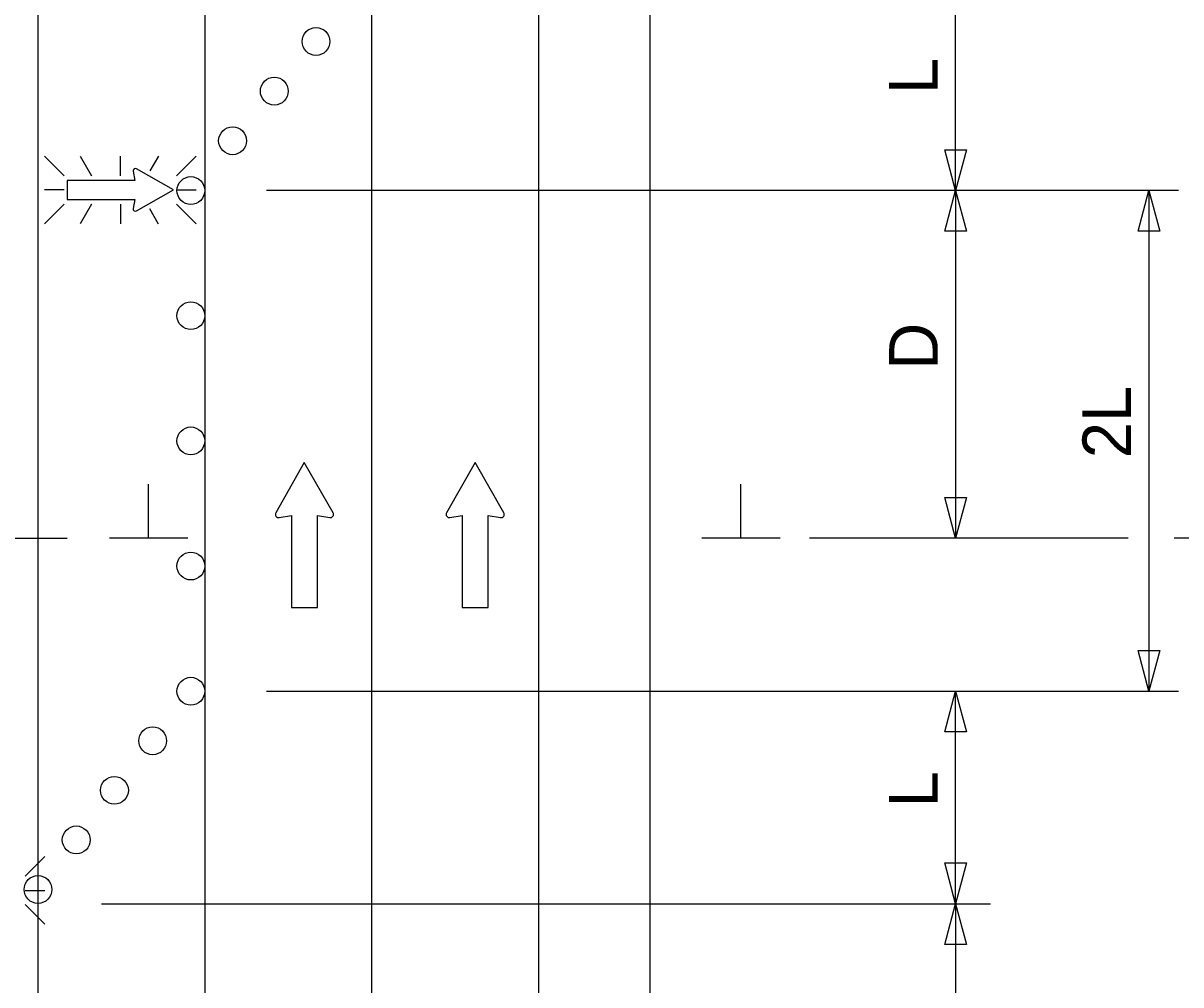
# Model space of a CAD drawing. Extents: x 16744 to 19504, y 5731 to 6974.
# Drawn here: x 17971.4 to 18137.9, y 6414.2 to 6552.5 of the extents above; entities that cross this region are included whole.
import ezdxf

# ---------------------------------------------------------------- set-up
doc = ezdxf.new("R2010")
doc.units = 0
for name, color, linetype in [('ALI_LEGAL_EX', 7, 'Continuous'), ('MT_SCRATCH_LEVEL_E', 7, 'Continuous'), ('PAVT_EDGE_EX', 7, 'Continuous'), ('TRAFFIC_SIGNS_PR', 7, 'Continuous'), ('TYPICAL_TEXT_DIMEN_PR', 7, 'Continuous')]:
    doc.layers.add(name, color=color, linetype=linetype)

msp = doc.modelspace()

# ---------------------------------------------------------------- linework, layer by layer
at = {"layer": 'ALI_LEGAL_EX'}
for p, q in [((17997.5, 6891.16), (17997.5, 6061.98)), ((18021.5, 6891.16), (18021.5, 6061.98)), ((18021.5, 6891.16), (18021.5, 6061.98))]:
    msp.add_line(p, q, dxfattribs=at)
for points in [[(17997.5, 6491.16), (17997.5, 6466.16)], [(18021.5, 6491.16), (18021.5, 6466.16)]]:
    msp.add_lwpolyline(points, dxfattribs=at)
at = {"layer": 'MT_SCRATCH_LEVEL_E'}
for p, q in [((18011.82, 6489.34), (18007.71, 6482.1)), ((18011.82, 6489.34), (18007.71, 6482.1)), ((18015.97, 6482.1), (18011.82, 6489.34)), ((18015.97, 6482.1), (18011.82, 6489.34)), ((18036.38, 6489.34), (18032.27, 6482.1)), ((18036.38, 6489.34), (18032.27, 6482.1)), ((18040.53, 6482.1), (18036.38, 6489.34)), ((18040.53, 6482.1), (18036.38, 6489.34)), ((18008.19, 6481.41), (18009.97, 6481.73)), ((18008.19, 6481.41), (18009.97, 6481.73)), ((18009.97, 6481.73), (18009.97, 6468.47)), ((18009.97, 6481.73), (18009.97, 6468.47)), ((18013.71, 6468.47), (18013.71, 6481.73)), ((18013.71, 6481.73), (18015.49, 6481.41)), ((18013.71, 6468.47), (18013.71, 6481.73)), ((18013.71, 6481.73), (18015.49, 6481.41)), ((18032.75, 6481.41), (18034.53, 6481.73)), ((18032.75, 6481.41), (18034.53, 6481.73)), ((18034.53, 6481.73), (18034.53, 6468.47)), ((18034.53, 6481.73), (18034.53, 6468.47)), ((18038.27, 6468.47), (18038.27, 6481.73)), ((18038.27, 6481.73), (18040.05, 6481.41)), ((18038.27, 6468.47), (18038.27, 6481.73)), ((18038.27, 6481.73), (18040.05, 6481.41)), ((18009.97, 6468.47), (18013.71, 6468.47)), ((18009.97, 6468.47), (18013.71, 6468.47)), ((18034.53, 6468.47), (18038.27, 6468.47)), ((18034.53, 6468.47), (18038.27, 6468.47))]:
    msp.add_line(p, q, dxfattribs=at)
for centre, start, end in [((18008.12, 6481.87), 150.4248, 279.9638), ((18008.12, 6481.87), 150.4248, 279.9638), ((18015.56, 6481.87), 260.0362, 29.7731), ((18015.56, 6481.87), 260.0362, 29.7731), ((18032.68, 6481.87), 150.4248, 279.9638), ((18032.68, 6481.87), 150.4248, 279.9638), ((18040.12, 6481.87), 260.0362, 29.7731), ((18040.12, 6481.87), 260.0362, 29.7731)]:
    msp.add_arc(centre, 0.463, start, end, dxfattribs=at)
at = {"layer": 'PAVT_EDGE_EX'}
for p, q in [((17973.5, 6891.16), (17973.5, 6061.98)), ((17973.5, 6891.16), (17973.5, 6061.98)), ((18045.5, 6891.16), (18045.5, 6061.98)), ((18061.5, 6891.16), (18061.5, 6061.98))]:
    msp.add_line(p, q, dxfattribs=at)
at = {"layer": 'TRAFFIC_SIGNS_PR'}
for p, q in [((17977.28, 6530.55), (17974.46, 6533.37)), ((17979.58, 6533.37), (17981.2, 6530.55)), ((17985.36, 6530.55), (17985.36, 6533.37)), ((17990.83, 6533.37), (17989.62, 6531.27)), ((17996.27, 6533.36), (17993.45, 6530.55)), ((17977.28, 6528.52), (17974.46, 6528.52)), ((17993.45, 6528.52), (17996.27, 6528.52)), ((17977.28, 6526.48), (17974.46, 6523.66)), ((17981.23, 6526.48), (17979.6, 6523.66)), ((17985.36, 6526.48), (17985.36, 6523.66)), ((17996.27, 6523.66), (17993.45, 6526.48)), ((17989.55, 6525.85), (17990.81, 6523.66)), ((17974.51, 6432.65), (17971.69, 6429.83)), ((17971.69, 6427.8), (17974.51, 6427.8)), ((17974.51, 6422.95), (17971.69, 6425.77))]:
    msp.add_line(p, q, dxfattribs=at)
for points in [[(17987.19, 6531.2), (17987.42, 6529.9), (17977.7, 6529.9), (17977.7, 6527.16), (17987.42, 6527.16), (17987.19, 6525.85)], [(17987.69, 6525.5), (17993, 6528.52), (17987.69, 6531.56)]]:
    msp.add_lwpolyline(points, dxfattribs=at)
for centre in [(18013.5, 6549.87), (18007.5, 6542.73), (18001.5, 6535.59), (17995.5, 6528.44), (17995.5, 6510.44), (17995.5, 6492.44), (17995.5, 6474.44), (17995.5, 6456.44), (17990.01, 6449.31), (17984.51, 6442.19), (17979.01, 6435.06), (17973.51, 6427.93)]:
    msp.add_circle(centre, 2, dxfattribs=at)
for centre, start, end in [((17987.53, 6531.26), 61.4833, 189.9593), ((17987.53, 6525.8), 170.7308, 298.8916)]:
    msp.add_arc(centre, 0.341, start, end, dxfattribs=at)
at = {"layer": 'TYPICAL_TEXT_DIMEN_PR'}
for p, q in [((18105.5, 6528.44), (18105.5, 6559.01)), ((18105.5, 6528.44), (18103.93, 6534.31)), ((18103.93, 6534.31), (18105.5, 6534.31)), ((18105.5, 6534.31), (18107.07, 6534.31)), ((18107.07, 6534.31), (18105.5, 6528.44)), ((18137.55, 6528.44), (18006.4, 6528.44)), ((18103.93, 6522.58), (18105.5, 6528.44)), ((18105.5, 6528.44), (18105.5, 6478.44)), ((18105.5, 6528.44), (18107.07, 6522.58)), ((18131.74, 6522.58), (18133.31, 6528.44)), ((18133.31, 6528.44), (18134.88, 6522.58)), ((18133.31, 6528.44), (18133.31, 6456.44)), ((18105.5, 6522.58), (18103.93, 6522.58)), ((18107.07, 6522.58), (18105.5, 6522.58)), ((18133.31, 6522.58), (18131.74, 6522.58)), ((18134.88, 6522.58), (18133.31, 6522.58)), ((17989.43, 6478.44), (17989.43, 6486.23)), ((18074.63, 6478.44), (18074.63, 6486.23)), ((18105.5, 6478.44), (18103.93, 6484.31)), ((18103.93, 6484.31), (18105.5, 6484.31)), ((18105.5, 6484.31), (18107.07, 6484.31)), ((18107.07, 6484.31), (18105.5, 6478.44)), ((18133.31, 6483.31), (18133.31, 6479.55)), ((17899.85, 6478.44), (17977.7, 6478.44)), ((17995.05, 6478.44), (17983.8, 6478.44)), ((18080.25, 6478.44), (18069, 6478.44)), ((18130.32, 6478.44), (18084.5, 6478.44)), ((18174.21, 6478.44), (18136.94, 6478.44)), ((18133.31, 6456.44), (18131.74, 6462.31)), ((18131.74, 6462.31), (18133.31, 6462.31)), ((18133.31, 6462.31), (18134.88, 6462.31)), ((18134.88, 6462.31), (18133.31, 6456.44)), ((18006.4, 6456.44), (18137.55, 6456.44)), ((18103.93, 6450.58), (18105.5, 6456.44)), ((18105.5, 6425.88), (18105.5, 6456.44)), ((18105.5, 6456.44), (18107.07, 6450.58)), ((18105.5, 6450.58), (18103.93, 6450.58)), ((18107.07, 6450.58), (18105.5, 6450.58)), ((18105.5, 6425.88), (18103.93, 6431.74)), ((18103.93, 6431.74), (18105.5, 6431.74)), ((18105.5, 6431.74), (18107.07, 6431.74)), ((18107.07, 6431.74), (18105.5, 6425.88)), ((17982.67, 6425.88), (18110.5, 6425.88)), ((18103.93, 6420.02), (18105.5, 6425.88)), ((18105.5, 6425.88), (18105.5, 6377.89)), ((18105.5, 6425.88), (18107.07, 6420.02)), ((18105.5, 6420.02), (18103.93, 6420.02)), ((18107.07, 6420.02), (18105.5, 6420.02))]:
    msp.add_line(p, q, dxfattribs=at)

# ---------------------------------------------------------------- texts
for s, p in [('L', (18102.94, 6542.3)), ('D', (18102.94, 6502.66)), ('2L', (18130.75, 6489.95)), ('L', (18102.94, 6439.74))]:
    msp.add_text(s, height=7, rotation=90, dxfattribs=at).set_placement(p)

doc.saveas('drawing.dxf')
